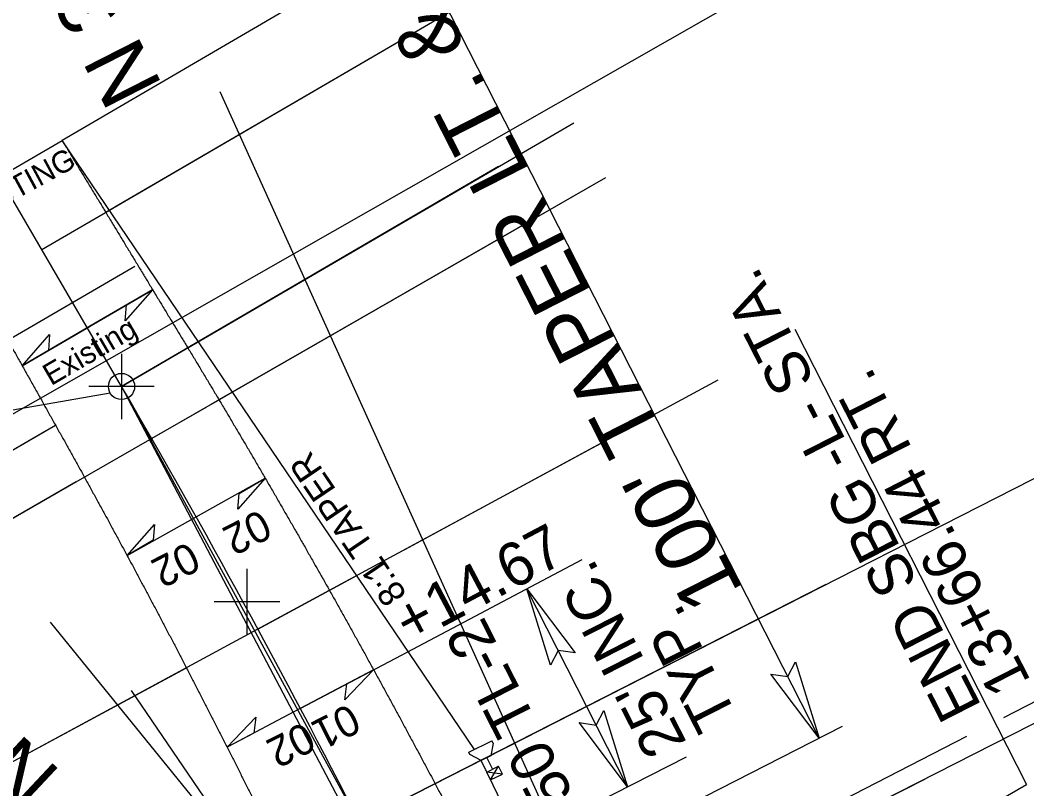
# Model space of a CAD drawing. Extents: x 557583 to 560285, y 513145 to 516544.
# Drawn here: x 559282.2 to 559397.5, y 515629.1 to 515717.2 of the extents above; entities that cross this region are included whole.
import ezdxf

# ---------------------------------------------------------------- set-up
doc = ezdxf.new("R2010")
doc.units = 0
for name, color, linetype in [('COGO Default Chain', 7, 'Continuous'), ('Exist Environmental Wetland Boundary Cogo Point CELL', 7, 'Continuous'), ('Exist Hydro Jurisdictional Stream or Body of Water NEU Mitigable Cogo Comment', 7, 'Continuous'), ('Exist Hydro Jurisdictional Stream or Body of Water NEU Mitigable Cogo Elevation', 7, 'Continuous'), ('Exist Hydro Jurisdictional Stream or Body of Water NEU Mitigable Cogo Point CELL', 7, 'Continuous'), ('Prop Dimension', 7, 'Continuous'), ('Prop DSN Text', 7, 'Continuous'), ('Prop EOT', 7, 'Continuous'), ('Prop Guardrail Anchor Unit CELL', 7, 'Continuous'), ('Prop Paved Shoulder', 7, 'Continuous'), ('Prop Superelevation Label', 7, 'Continuous'), ('Prop Terminator CELL', 7, 'Continuous'), ('Scratch_Level_1', 7, 'Continuous'), ('Scratch_Level_2', 7, 'Continuous'), ('Scratch_Level_3', 7, 'Continuous'), ('Scratch_Level_4', 7, 'Continuous'), ('Scratch_Level_7', 7, 'Continuous'), ('Scratch_Level_8', 7, 'Continuous')]:
    doc.layers.add(name, color=color, linetype=linetype)

msp = doc.modelspace()

# ---------------------------------------------------------------- linework, layer by layer
at = {"layer": 'COGO Default Chain'}
for p, q in [((559293.8, 515678.93), (559293.8, 515671.43)), ((559297.55, 515675.18), (559290.05, 515675.18)), ((559308.18, 515654.27), (559308.18, 515646.77)), ((559311.93, 515650.52), (559304.43, 515650.52))]:
    msp.add_line(p, q, dxfattribs=at)
msp.add_arc((558429.99, 515171.37), 1000, 26.98193, 30.25241, dxfattribs=at)
at = {"layer": 'Exist Environmental Wetland Boundary Cogo Point CELL'}
for p, q in [((559292.5, 515674.42), (559204.18, 515658.96)), ((559394.92, 515637.26), (559464.46, 515672.89)), ((559331.48, 515604.76), (559390.68, 515635.1))]:
    msp.add_line(p, q, dxfattribs=at)
msp.add_circle((559293.8, 515675.18), 1.5, dxfattribs=at)
msp.add_circle((559293.8, 515675.18), 1.5, dxfattribs=at)
at = {"layer": 'Exist Hydro Jurisdictional Stream or Body of Water NEU Mitigable Cogo Elevation'}
msp.add_line((559293.8, 515675.18), (559264.68, 515725.1), dxfattribs=at)
msp.add_arc((558429.99, 515171.37), 1000, 26.98193, 30.25241, dxfattribs=at)
at = {"layer": 'Exist Hydro Jurisdictional Stream or Body of Water NEU Mitigable Cogo Point CELL'}
for p, q in [((559297.36, 515686.27), (559289.59, 515681.74)), ((559282.42, 515677.56), (559290.19, 515682.09)), ((559294.44, 515655.81), (559310.26, 515664.68)), ((559322.69, 515642.71), (559314.29, 515638.28)), ((559314.29, 515638.28), (559305.9, 515633.85))]:
    msp.add_line(p, q, dxfattribs=at)
for points in [[(559297.36, 515686.27), (559294.23, 515682.71), (559294.36, 515684.52)], [(559282.42, 515677.56), (559285.55, 515681.12), (559285.42, 515679.3)], [(559310.26, 515664.68), (559307.13, 515661.11), (559307.27, 515662.93)], [(559294.44, 515655.81), (559297.57, 515659.37), (559297.44, 515657.56)], [(559322.69, 515642.71), (559319.41, 515639.28), (559319.62, 515641.09)], [(559305.9, 515633.85), (559309.18, 515637.28), (559308.97, 515635.47)]]:
    msp.add_lwpolyline(points, close=True, dxfattribs=at)
at = {"layer": 'Prop Dimension'}
for p, q in [((559335.66, 515731.77), (559286.99, 515703.38)), ((559373.74, 515634.89), (559327.15, 515726.39)), ((559282.73, 515677.74), (559297.04, 515686.09)), ((559370.95, 515681.73), (559397.5, 515629.56)), ((559325.24, 515644.06), (559346.6, 515655.34)), ((559351.79, 515629.32), (559340.25, 515651.98)), ((559314.29, 515638.28), (559325.24, 515644.06)), ((559336.91, 515616.13), (559376.42, 515636.25)), ((559325.73, 515616.05), (559358.53, 515632.75)), ((559348.99, 515601.82), (559397.5, 515629.56))]:
    msp.add_line(p, q, dxfattribs=at)
at = {"layer": 'Prop DSN Text'}
msp.add_line((559319.09, 515607.06), (559285.65, 515648.17), dxfattribs=at)
at = {"layer": 'Prop EOT'}
msp.add_line((559272.64, 515695.01), (559286.99, 515703.38), dxfattribs=at)
for points in [[(559286.99, 515703.38), (559287.34, 515702.8), (559287.69, 515702.23), (559288.04, 515701.65), (559288.39, 515701.07), (559288.74, 515700.49), (559289.09, 515699.91), (559289.44, 515699.34), (559289.79, 515698.76), (559290.14, 515698.18), (559290.49, 515697.6), (559290.84, 515697.02), (559291.2, 515696.45), (559291.55, 515695.87), (559291.9, 515695.29), (559292.25, 515694.71), (559292.6, 515694.13), (559292.95, 515693.56), (559293.3, 515692.98), (559293.65, 515692.4), (559294, 515691.82), (559294.35, 515691.24), (559294.7, 515690.67), (559295.05, 515690.09), (559295.4, 515689.51), (559295.75, 515688.93), (559296.1, 515688.35), (559296.45, 515687.78), (559296.8, 515687.2), (559297.15, 515686.62), (559297.5, 515686.04), (559297.85, 515685.46), (559298.2, 515684.89), (559298.55, 515684.31), (559298.9, 515683.73), (559299.25, 515683.15), (559299.6, 515682.57), (559299.95, 515682), (559300.3, 515681.42), (559300.65, 515680.84), (559301, 515680.26), (559301.35, 515679.69), (559301.7, 515679.1), (559302.06, 515678.52), (559302.41, 515677.94), (559302.76, 515677.35), (559303.11, 515676.77), (559303.46, 515676.18), (559303.81, 515675.6), (559304.16, 515675.01), (559304.51, 515674.43), (559304.86, 515673.84), (559305.21, 515673.26), (559305.56, 515672.67), (559305.91, 515672.09), (559306.26, 515671.5), (559306.6, 515670.91), (559306.95, 515670.33), (559307.3, 515669.74), (559307.64, 515669.15), (559307.99, 515668.56), (559308.34, 515667.98), (559308.68, 515667.39), (559309.03, 515666.8), (559309.37, 515666.21), (559309.71, 515665.62), (559310.06, 515665.03), (559310.4, 515664.44), (559310.74, 515663.85), (559311.09, 515663.26), (559311.43, 515662.67), (559311.77, 515662.08), (559312.11, 515661.49), (559312.45, 515660.9), (559312.79, 515660.31)], [(559272.64, 515695.01), (559272.97, 515694.42), (559273.3, 515693.83), (559273.63, 515693.24), (559273.96, 515692.65), (559274.29, 515692.06), (559274.62, 515691.47), (559274.95, 515690.88), (559275.28, 515690.29), (559275.61, 515689.7), (559275.94, 515689.11), (559276.27, 515688.52), (559276.6, 515687.93), (559276.93, 515687.35), (559277.26, 515686.76), (559277.59, 515686.17), (559277.92, 515685.58), (559278.25, 515684.99), (559278.58, 515684.4), (559278.91, 515683.81), (559279.25, 515683.22), (559279.58, 515682.63), (559279.91, 515682.04), (559280.24, 515681.45), (559280.57, 515680.86), (559280.9, 515680.27), (559281.23, 515679.68), (559281.56, 515679.09), (559281.89, 515678.5), (559282.22, 515677.91), (559282.55, 515677.32), (559282.88, 515676.73), (559283.21, 515676.15), (559283.54, 515675.56), (559283.87, 515674.97), (559284.2, 515674.38), (559284.53, 515673.79), (559284.86, 515673.2), (559285.19, 515672.61), (559285.52, 515672.02), (559285.85, 515671.43), (559286.18, 515670.84), (559286.51, 515670.25), (559286.84, 515669.67), (559287.17, 515669.09), (559287.49, 515668.5), (559287.82, 515667.92), (559288.14, 515667.33), (559288.47, 515666.74), (559288.79, 515666.16), (559289.12, 515665.57), (559289.44, 515664.99), (559289.76, 515664.4), (559290.09, 515663.81), (559290.41, 515663.22), (559290.73, 515662.64), (559291.05, 515662.05), (559291.37, 515661.46), (559291.69, 515660.87), (559292.02, 515660.29), (559292.34, 515659.7), (559292.65, 515659.11), (559292.97, 515658.52), (559293.29, 515657.93), (559293.61, 515657.34), (559293.93, 515656.75), (559294.25, 515656.16), (559294.56, 515655.57), (559294.88, 515654.99), (559295.2, 515654.39), (559295.51, 515653.8), (559295.83, 515653.21), (559296.14, 515652.62), (559296.46, 515652.03), (559296.77, 515651.44)], [(559312.79, 515660.31), (559313.13, 515659.72), (559313.47, 515659.13), (559313.81, 515658.54), (559314.15, 515657.95), (559314.49, 515657.35), (559314.83, 515656.76), (559315.16, 515656.17), (559315.5, 515655.58), (559315.84, 515654.98), (559316.17, 515654.39), (559316.51, 515653.8), (559316.85, 515653.2), (559317.18, 515652.61), (559317.52, 515652.02), (559317.85, 515651.42), (559318.18, 515650.83), (559318.52, 515650.23), (559318.85, 515649.64), (559319.18, 515649.04), (559319.52, 515648.44), (559319.85, 515647.85), (559320.18, 515647.25), (559320.51, 515646.66), (559320.84, 515646.06), (559321.17, 515645.46), (559321.5, 515644.87), (559321.83, 515644.27), (559322.16, 515643.67), (559322.49, 515643.07), (559322.82, 515642.48), (559323.15, 515641.88), (559323.48, 515641.28), (559323.8, 515640.68), (559324.13, 515640.08), (559324.46, 515639.48), (559324.78, 515638.88), (559325.11, 515638.28), (559325.43, 515637.69), (559325.76, 515637.09), (559326.08, 515636.49), (559326.41, 515635.88), (559326.73, 515635.28), (559327.05, 515634.68), (559327.38, 515634.08), (559327.7, 515633.48), (559328.02, 515632.88), (559328.34, 515632.28), (559328.66, 515631.68), (559328.99, 515631.07), (559329.31, 515630.47), (559329.63, 515629.87), (559329.94, 515629.27), (559330.26, 515628.67), (559330.58, 515628.07), (559330.89, 515627.48), (559331.21, 515626.88), (559331.53, 515626.28), (559331.84, 515625.69), (559332.16, 515625.09), (559332.48, 515624.49), (559332.79, 515623.89), (559333.11, 515623.3), (559333.43, 515622.7), (559333.74, 515622.1), (559334.06, 515621.51), (559334.38, 515620.91), (559334.69, 515620.31), (559335.01, 515619.72), (559335.33, 515619.12), (559335.64, 515618.52), (559335.96, 515617.92), (559336.28, 515617.33), (559336.91, 515616.13)], [(559296.77, 515651.44), (559297.09, 515650.85), (559297.4, 515650.26), (559297.72, 515649.67), (559298.03, 515649.07), (559298.34, 515648.48), (559298.65, 515647.89), (559298.96, 515647.3), (559299.28, 515646.7), (559299.59, 515646.11), (559299.9, 515645.52), (559300.21, 515644.92), (559300.52, 515644.33), (559300.83, 515643.74), (559301.13, 515643.14), (559301.44, 515642.55), (559301.75, 515641.95), (559302.06, 515641.36), (559302.37, 515640.77), (559302.67, 515640.17), (559302.98, 515639.58), (559303.28, 515638.98), (559303.59, 515638.38), (559303.9, 515637.79), (559304.2, 515637.19), (559304.5, 515636.6), (559304.81, 515636), (559305.11, 515635.4), (559305.42, 515634.81), (559305.72, 515634.21), (559306.02, 515633.61), (559306.32, 515633.01), (559306.62, 515632.42), (559306.92, 515631.82), (559307.23, 515631.22), (559307.53, 515630.62), (559307.83, 515630.02), (559308.13, 515629.43), (559308.42, 515628.83), (559308.72, 515628.23), (559309.02, 515627.63), (559309.32, 515627.03), (559309.62, 515626.43), (559309.91, 515625.83), (559310.21, 515625.23), (559310.51, 515624.63), (559310.8, 515624.03), (559311.1, 515623.43), (559311.39, 515622.83), (559311.69, 515622.23), (559311.98, 515621.63), (559312.27, 515621.03), (559312.57, 515620.42), (559312.87, 515619.81), (559313.16, 515619.21), (559313.46, 515618.6), (559313.75, 515617.99), (559314.05, 515617.38), (559314.35, 515616.78), (559314.64, 515616.17), (559314.94, 515615.56), (559315.24, 515614.96), (559315.53, 515614.35), (559315.83, 515613.74), (559316.12, 515613.13), (559316.42, 515612.53), (559316.72, 515611.92), (559317.01, 515611.31), (559317.31, 515610.7), (559317.61, 515610.1), (559317.9, 515609.49), (559318.2, 515608.88), (559318.49, 515608.27), (559319.09, 515607.06)]]:
    msp.add_spline(points, degree=3, dxfattribs=at)
at = {"layer": 'Prop Guardrail Anchor Unit CELL'}
for p, q in [((559333.6, 515633.29), (559336.25, 515634.57)), ((559336.38, 515634.29), (559336.12, 515632.86)), ((559336.38, 515634.29), (559336.25, 515634.57)), ((559333.73, 515633.01), (559333.6, 515633.29)), ((559335.02, 515632.33), (559333.73, 515633.01)), ((559336.12, 515632.86), (559335.02, 515632.33)), ((559335.66, 515631), (559335.02, 515632.33)), ((559335.67, 515632.64), (559336.31, 515631.32)), ((559335.65, 515631), (559337.01, 515631.66)), ((559336.08, 515630.1), (559335.65, 515631)), ((559337.45, 515630.76), (559335.65, 515631)), ((559336.08, 515630.1), (559337.01, 515631.66)), ((559336.08, 515630.1), (559337.45, 515630.76)), ((559337.45, 515630.76), (559337.01, 515631.66)), ((559335.87, 515630.55), (559346.76, 515608.05))]:
    msp.add_line(p, q, dxfattribs=at)
at = {"layer": 'Prop Paved Shoulder'}
msp.add_line((559334.24, 515633.6), (559286.99, 515703.38), dxfattribs=at)
at = {"layer": 'Prop Superelevation Label'}
for q in [(559297.36, 515686.27), (559282.42, 515677.56)]:
    msp.add_line((559289.88, 515681.91), q, dxfattribs=at)
at = {"layer": 'Prop Terminator CELL'}
for points in [[(559342.95, 515643.26), (559340.25, 515651.98), (559345.78, 515644.65), (559343.83, 515644.94)], [(559371.04, 515643.61), (559373.74, 515634.89), (559368.21, 515642.22), (559370.16, 515641.93)], [(559349.09, 515638.04), (559351.79, 515629.32), (559346.26, 515636.66), (559348.21, 515636.36)]]:
    msp.add_lwpolyline(points, close=True, dxfattribs=at)
at = {"layer": 'Scratch_Level_1'}
for p, q in [((559349.28, 515699.1), (559245.21, 515639.35)), ((559256.65, 515618.83), (559362.18, 515675.95)), ((559374.51, 515652.49), (559267.58, 515598.02)), ((559346, 515609.91), (559385.85, 515630.2))]:
    msp.add_line(p, q, dxfattribs=at)
at = {"layer": 'Scratch_Level_2'}
for p, q in [((559098.28, 515511.79), (559543.81, 515738.73)), ((559555.17, 515716.41), (559109.6, 515489.55)), ((559327.86, 515716.02), (559292.36, 515695.32)), ((559302.44, 515680.22), (559336.99, 515700.37)), ((559340.61, 515694.12), (559305.92, 515674.2)), ((559250.61, 515649.99), (559285.16, 515670.14)), ((559288.57, 515664.25), (559253.88, 515644.33))]:
    msp.add_line(p, q, dxfattribs=at)
at = {"layer": 'Scratch_Level_3'}
for p, q in [((559295.32, 515688.94), (559280.95, 515680.56)), ((559293.8, 515675.18), (559356.28, 515556.58)), ((559293.8, 515675.18), (559346.84, 515577.85))]:
    msp.add_line(p, q, dxfattribs=at)
at = {"layer": 'Scratch_Level_4'}
for p, q in [((559394.6, 515736.6), (558806.81, 515401.49)), ((559327.86, 515716.02), (559293.04, 515695.71)), ((559336.99, 515700.37), (559293.8, 515675.18)), ((559305.05, 515681.74), (559336.99, 515700.37)), ((559292.43, 515695.36), (559284.67, 515690.83)), ((559293.8, 515675.18), (559302.61, 515680.32)), ((559304.08, 515673.15), (559306.51, 515674.55)), ((559297.24, 515669.22), (559303.57, 515672.86)), ((559326.27, 515656.51), (559353.39, 515671.19)), ((559309.42, 515647.39), (559320.75, 515653.52)), ((559336.93, 515633.35), (559365.6, 515647.95)), ((559351.37, 515557.79), (559294.93, 515640.35)), ((559321.04, 515625.26), (559335.05, 515632.39))]:
    msp.add_line(p, q, dxfattribs=at)
at = {"layer": 'Scratch_Level_7'}
for p, q in [((559336.5, 515721.06), (559292, 515695.11)), ((559301.4, 515679.61), (559345.63, 515705.41)), ((559349.28, 515699.1), (559304.97, 515673.66)), ((559317.62, 515651.83), (559362.18, 515675.95)), ((559241.97, 515644.95), (559286.23, 515670.76)), ((559289.54, 515664.8), (559245.21, 515639.35)), ((559338.02, 515633.9), (559356.69, 515643.41)), ((559256.65, 515618.83), (559301.23, 515642.96)), ((559329.73, 515629.68), (559335.05, 515632.39))]:
    msp.add_line(p, q, dxfattribs=at)
at = {"layer": 'Scratch_Level_8'}
msp.add_line((559428.04, 515437.39), (559305.09, 515708.93), dxfattribs=at)

# ---------------------------------------------------------------- texts
at = {"layer": 'Exist Hydro Jurisdictional Stream or Body of Water NEU Mitigable Cogo Comment'}
for s, rotation, p in [('N 30%%d 15\' 08.7" W', 116.9819, (559298.55, 515709.63)), ('N 46%%d 50\' 16.8" W', 136.838, (559287.02, 515630.95))]:
    msp.add_text(s, height=7, rotation=rotation, dxfattribs=at).set_placement(p)
at = {"layer": 'Prop Dimension'}
for s, height, rotation, p in [("100' TAPER LT. & RT.", 7, 116.9819, (559365.11, 515651.79)), ('8:1 TAPER', 3, 124.1069, (559326.59, 515651.34)), ('+14.67', 5, 27.8839, (559326.8, 515645.58)), ("25' INC. ", 5, 116.9819, (559358.62, 515634.34)), ('TYP.', 5, 116.9819, (559364.46, 515637.31))]:
    msp.add_text(s, height=height, rotation=rotation, dxfattribs=at).set_placement(p)
at = {"layer": 'Prop DSN Text'}
for s, height, rotation, p in [('EXISTING', 2.5, 28.4259, (559275.07, 515693.02)), ('END SBG -L- STA.', 5, 117.0233, (559392.41, 515638.5)), ('13+66.44 RT.', 5, 117.0233, (559398.06, 515641.38))]:
    msp.add_text(s, height=height, rotation=rotation, dxfattribs=at).set_placement(p)
at = {"layer": 'Prop Guardrail Anchor Unit CELL'}
msp.add_text('GRAU 350 TL-2', height=5, rotation=116.9819, dxfattribs=at).set_placement((559356.96, 515606.27))
at = {"layer": 'Prop Superelevation Label'}
for s, height, rotation, p in [('Existing', 2.5, 30.2524, (559285.73, 515675.21)), ('02', 3.5, 206.9819, (559309.75, 515661.18)), ('02', 3.5, 206.9819, (559301.55, 515657.47)), ('01', 3.5, 206.9819, (559319.93, 515638.93)), ('02', 3.5, 206.9819, (559314.76, 515636.83))]:
    msp.add_text(s, height=height, rotation=rotation, dxfattribs=at).set_placement(p)

doc.saveas('drawing.dxf')
